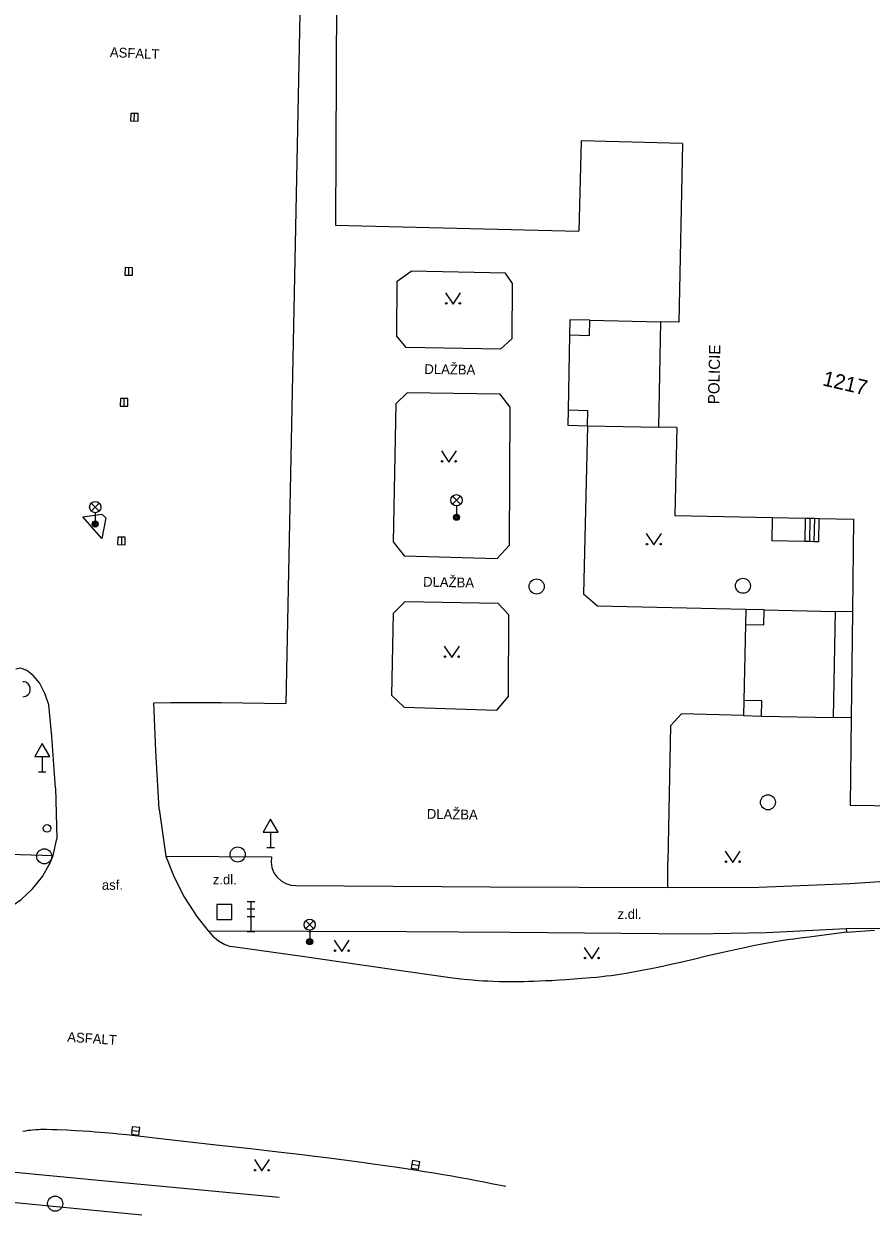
# Model space of a CAD drawing. Extents: x -538441 to -536770, y -1181008 to -1179809.
# Drawn here: x -537395.9 to -537339.6, y -1180903.8 to -1180824.7 of the extents above; entities that cross this region are included whole.
import ezdxf

# ---------------------------------------------------------------- set-up
doc = ezdxf.new("R2010")
doc.units = 0
for name, color, linetype in [('Vrstva 10', 7, 'Continuous'), ('Vrstva 11', 7, 'Continuous'), ('Vrstva 22', 7, 'Continuous'), ('Vrstva 26', 7, 'Continuous'), ('Vrstva 27', 7, 'Continuous'), ('Vrstva 28', 7, 'Continuous'), ('Vrstva 30', 7, 'Continuous'), ('Vrstva 33', 7, 'Continuous'), ('Vrstva 34', 7, 'Continuous'), ('Vrstva 36', 7, 'Continuous'), ('Vrstva 40', 7, 'Continuous'), ('Vrstva 41', 7, 'Continuous'), ('Vrstva 47', 7, 'Continuous'), ('Vrstva 5', 7, 'Continuous')]:
    doc.layers.add(name, color=color, linetype=linetype)

msp = doc.modelspace()

# ---------------------------------------------------------------- linework, layer by layer
at = {"layer": 'Vrstva 10'}
for p, q in [((-537393.79, -1180875.4), (-537393.689, -1180878.783)), ((-537386.911, -1180876.805), (-537386.453, -1180879.925)), ((-537393.943, -1180879.887), (-537393.689, -1180878.783)), ((-537341.271, -1180884.988), (-537339.403, -1180884.851))]:
    msp.add_line(p, q, dxfattribs=at)
for points in [[(-537393.79, -1180875.4), (-537394.04, -1180871.991), (-537394.231, -1180869.894), (-537394.465, -1180869.187), (-537394.848, -1180868.417), (-537395.259, -1180867.947), (-537395.699, -1180867.612), (-537396.093, -1180867.461), (-537396.423, -1180867.524)], [(-537386.911, -1180876.805), (-537387.135, -1180872.945), (-537387.26, -1180869.75)], [(-537396.933, -1180883.407), (-537396.07, -1180882.818), (-537395.306, -1180882.105), (-537394.66, -1180881.283), (-537394.147, -1180880.373), (-537393.943, -1180879.887)], [(-537386.453, -1180879.925), (-537385.911, -1180881.334), (-537385.223, -1180882.678), (-537384.397, -1180883.942), (-537383.644, -1180884.884)], [(-537383.644, -1180884.884), (-537383.333, -1180885.246), (-537382.967, -1180885.552), (-537382.554, -1180885.792), (-537382.173, -1180885.941)], [(-537341.271, -1180884.988), (-537343.735, -1180885.325), (-537344.33, -1180885.39), (-537344.768, -1180885.443), (-537345.191, -1180885.501), (-537345.601, -1180885.562), (-537345.997, -1180885.626), (-537346.381, -1180885.692), (-537346.752, -1180885.759), (-537347.111, -1180885.828), (-537347.459, -1180885.897), (-537348.133, -1180886.036)], [(-537373.444, -1180887.174), (-537377.552, -1180886.587), (-537382.173, -1180885.941)], [(-537348.133, -1180886.036), (-537348.763, -1180886.174), (-537349.354, -1180886.307), (-537350.461, -1180886.564), (-537351.43, -1180886.791), (-537352.278, -1180886.988), (-537353.02, -1180887.156), (-537353.671, -1180887.297), (-537354.24, -1180887.416), (-537354.739, -1180887.515), (-537355.176, -1180887.597), (-537355.558, -1180887.665), (-537355.894, -1180887.722), (-537356.187, -1180887.769), (-537356.444, -1180887.808), (-537356.895, -1180887.871), (-537357.233, -1180887.915), (-537357.487, -1180887.945), (-537357.868, -1180887.985)], [(-537367.59, -1180888.01), (-537369.6, -1180887.723), (-537371.61, -1180887.436), (-537372.527, -1180887.305), (-537373.444, -1180887.174)], [(-537357.868, -1180887.985), (-537358.25, -1180888.02), (-537358.831, -1180888.068), (-537359.377, -1180888.11), (-537359.889, -1180888.146), (-537360.371, -1180888.177), (-537360.823, -1180888.204), (-537361.246, -1180888.225), (-537361.644, -1180888.243), (-537362.017, -1180888.256), (-537362.367, -1180888.267), (-537362.695, -1180888.274), (-537363.002, -1180888.278), (-537363.29, -1180888.28), (-537363.831, -1180888.279), (-537364.303, -1180888.271), (-537364.716, -1180888.258), (-537365.077, -1180888.243), (-537365.392, -1180888.227), (-537365.668, -1180888.209), (-537365.909, -1180888.192), (-537366.331, -1180888.157), (-537366.646, -1180888.126), (-537366.883, -1180888.1), (-537367.237, -1180888.058), (-537367.59, -1180888.01)], [(-537395.953, -1180898.199), (-537395.76, -1180898.166), (-537395.591, -1180898.14), (-537395.443, -1180898.121), (-537395.312, -1180898.107), (-537395.083, -1180898.087), (-537394.911, -1180898.077), (-537394.781, -1180898.071), (-537394.586, -1180898.068), (-537394.39, -1180898.07), (-537394.022, -1180898.08), (-537393.676, -1180898.091), (-537393.027, -1180898.118)], [(-537393.027, -1180898.118), (-537392.459, -1180898.147), (-537391.962, -1180898.177), (-537391.528, -1180898.206), (-537391.147, -1180898.234), (-537390.482, -1180898.288), (-537389.983, -1180898.333), (-537389.609, -1180898.369), (-537389.049, -1180898.427), (-537388.49, -1180898.49), (-537386.609, -1180898.705), (-537383.315, -1180899.073)], [(-537383.315, -1180899.073), (-537380.845, -1180899.351), (-537378.993, -1180899.565), (-537377.604, -1180899.73), (-537376.564, -1180899.857), (-537375.783, -1180899.955), (-537374.613, -1180900.106), (-537373.444, -1180900.262)], [(-537373.444, -1180900.262), (-537372.562, -1180900.384), (-537371.241, -1180900.575), (-537369.92, -1180900.77), (-537369.278, -1180900.868), (-537368.656, -1180900.967), (-537368.055, -1180901.067), (-537367.473, -1180901.167), (-537366.91, -1180901.267), (-537366.365, -1180901.367), (-537365.838, -1180901.467), (-537365.328, -1180901.566), (-537364.834, -1180901.664), (-537363.878, -1180901.859)]]:
    msp.add_lwpolyline(points, dxfattribs=at)
at = {"layer": 'Vrstva 11'}
for p, q in [((-537377.522, -1180822.026), (-537378.49, -1180869.79)), ((-537371.1, -1180841.75), (-537370.16, -1180841.1)), ((-537363.9, -1180841.22), (-537370.16, -1180841.1)), ((-537363.44, -1180841.9), (-537363.9, -1180841.22)), ((-537371.12, -1180845.41), (-537371.1, -1180841.75)), ((-537363.46, -1180845.56), (-537363.44, -1180841.9)), ((-537370.5, -1180846.15), (-537371.12, -1180845.41)), ((-537363.46, -1180845.56), (-537364.24, -1180846.27)), ((-537364.24, -1180846.27), (-537370.5, -1180846.15)), ((-537370.43, -1180849.17), (-537371.19, -1180849.91)), ((-537364.26, -1180849.26), (-537370.43, -1180849.17)), ((-537363.6, -1180850.11), (-537364.26, -1180849.26)), ((-537371.19, -1180849.91), (-537371.37, -1180859.06)), ((-537363.65, -1180859.29), (-537363.6, -1180850.11)), ((-537358.458, -1180851.353), (-537358.73, -1180862.54)), ((-537391.98, -1180857.4), (-537390.7, -1180857.22)), ((-537390.7, -1180857.22), (-537390.44, -1180857.47)), ((-537390.71, -1180858.84), (-537391.98, -1180857.4)), ((-537390.44, -1180857.47), (-537390.71, -1180858.84)), ((-537346.199, -1180857.44), (-537346.23, -1180859)), ((-537343.999, -1180857.485), (-537344.03, -1180859.044)), ((-537343.699, -1180857.491), (-537343.73, -1180859.05)), ((-537343.399, -1180857.497), (-537343.43, -1180859.056)), ((-537343.1, -1180857.503), (-537343.131, -1180859.062)), ((-537371.37, -1180859.06), (-537370.63, -1180859.99)), ((-537364.45, -1180860.16), (-537363.65, -1180859.29)), ((-537370.63, -1180859.99), (-537364.45, -1180860.16)), ((-537357.8, -1180863.33), (-537358.73, -1180862.54)), ((-537370.59, -1180863.04), (-537371.37, -1180863.83)), ((-537364.4, -1180863.16), (-537370.59, -1180863.04)), ((-537363.69, -1180863.9), (-537364.4, -1180863.16)), ((-537347.946, -1180863.55), (-537357.8, -1180863.33)), ((-537371.37, -1180863.83), (-537371.48, -1180869.24)), ((-537363.71, -1180869.34), (-537363.69, -1180863.9)), ((-537371.48, -1180869.24), (-537370.63, -1180870.05)), ((-537364.48, -1180870.23), (-537363.71, -1180869.34)), ((-537370.63, -1180870.05), (-537364.48, -1180870.23)), ((-537352.23, -1180870.49), (-537352.95, -1180871.28)), ((-537348.111, -1180870.602), (-537352.23, -1180870.49)), ((-537352.95, -1180871.28), (-537353.137, -1180880.318)), ((-537401.921, -1180879.666), (-537393.943, -1180879.887)), ((-537386.453, -1180879.925), (-537379.453, -1180879.986)), ((-537353.118, -1180882.017), (-537353.137, -1180880.318)), ((-537341.045, -1180881.75), (-537338.714, -1180881.588)), ((-537377.821, -1180881.878), (-537364.922, -1180881.975)), ((-537364.922, -1180881.975), (-537353.118, -1180882.017)), ((-537353.118, -1180882.017), (-537347.079, -1180882.004)), ((-537347.079, -1180882.004), (-537341.045, -1180881.75)), ((-537383.644, -1180884.884), (-537370.477, -1180884.948)), ((-537346.568, -1180885.001), (-537341.292, -1180884.749)), ((-537341.292, -1180884.749), (-537341.271, -1180884.988)), ((-537370.477, -1180884.948), (-537363.578, -1180884.983)), ((-537363.578, -1180884.983), (-537351.311, -1180885.099)), ((-537351.311, -1180885.099), (-537346.568, -1180885.001)), ((-537401.07, -1180900.47), (-537390, -1180901.53)), ((-537390, -1180901.53), (-537378.93, -1180902.59)), ((-537388.06, -1180903.775), (-537397.13, -1180902.88))]:
    msp.add_line(p, q, dxfattribs=at)
for points in [[(-537343.131, -1180859.062), (-537343.43, -1180859.056), (-537343.73, -1180859.05), (-537344.03, -1180859.044), (-537346.23, -1180859)], [(-537387.26, -1180869.75), (-537386.14, -1180869.737), (-537385.58, -1180869.732), (-537385.02, -1180869.73), (-537384.204, -1180869.732), (-537382.775, -1180869.742), (-537378.49, -1180869.79)], [(-537379.453, -1180879.986), (-537379.475, -1180880.344), (-537379.417, -1180880.699), (-537379.282, -1180881.032), (-537379.091, -1180881.31), (-537378.812, -1180881.569), (-537378.5, -1180881.746), (-537378.157, -1180881.851), (-537377.821, -1180881.878)], [(-537328.346, -1180885.295), (-537328.896, -1180885.216), (-537329.31, -1180885.161), (-537329.621, -1180885.123), (-537330.087, -1180885.071), (-537330.555, -1180885.023), (-537330.979, -1180884.984), (-537331.391, -1180884.949), (-537331.79, -1180884.918), (-537332.177, -1180884.891), (-537332.552, -1180884.868), (-537332.916, -1180884.847), (-537333.269, -1180884.83), (-537333.611, -1180884.815), (-537334.273, -1180884.791), (-537334.895, -1180884.776), (-537335.478, -1180884.768), (-537336.025, -1180884.765), (-537336.538, -1180884.766), (-537337.019, -1180884.771), (-537341.292, -1180884.749)]]:
    msp.add_lwpolyline(points, dxfattribs=at)
at = {"layer": 'Vrstva 22'}
msp.add_arc((-537395.96, -1180868.85), 0.5, 270, 90, dxfattribs=at)
at = {"layer": 'Vrstva 26'}
msp.add_lwpolyline([(-537383.071, -1180884.146), (-537382.071, -1180884.146), (-537382.071, -1180883.146), (-537383.071, -1180883.146)], close=True, dxfattribs=at)
at = {"layer": 'Vrstva 27'}
for p, q in [((-537388.555, -1180831.12), (-537388.545, -1180830.62)), ((-537388.925, -1180841.36), (-537388.915, -1180840.86)), ((-537389.235, -1180850.05), (-537389.225, -1180849.55)), ((-537389.405, -1180858.75), (-537389.415, -1180859.25)), ((-537388.718, -1180898.151), (-537388.222, -1180898.207)), ((-537370.13, -1180900.399), (-537369.636, -1180900.475))]:
    msp.add_line(p, q, dxfattribs=at)
for points in [[(-537388.305, -1180831.125), (-537388.295, -1180830.625), (-537388.795, -1180830.615), (-537388.805, -1180831.115)], [(-537388.675, -1180841.365), (-537388.665, -1180840.865), (-537389.165, -1180840.855), (-537389.175, -1180841.355)], [(-537388.985, -1180850.055), (-537388.975, -1180849.555), (-537389.475, -1180849.545), (-537389.485, -1180850.045)], [(-537389.655, -1180858.745), (-537389.665, -1180859.245), (-537389.165, -1180859.255), (-537389.155, -1180858.755)], [(-537388.746, -1180898.4), (-537388.249, -1180898.455), (-537388.194, -1180897.958), (-537388.691, -1180897.903)], [(-537370.168, -1180900.646), (-537369.674, -1180900.722), (-537369.598, -1180900.228), (-537370.092, -1180900.152)]]:
    msp.add_lwpolyline(points, close=True, dxfattribs=at)
for centre in [(-537361.84, -1180862.03), (-537348.14, -1180861.98), (-537346.48, -1180876.36), (-537381.689, -1180879.824), (-537393.81, -1180903.01)]:
    msp.add_circle(centre, 0.5, dxfattribs=at)
at = {"layer": 'Vrstva 28'}
msp.add_circle((-537394.35, -1180878.09), 0.25, dxfattribs=at)
at = {"layer": 'Vrstva 30'}
msp.add_circle((-537394.533, -1180879.945), 0.5, dxfattribs=at)
at = {"layer": 'Vrstva 33'}
for p, q in [((-537367.425, -1180856.57), (-537366.895, -1180856.04)), ((-537367.425, -1180856.04), (-537366.895, -1180856.57)), ((-537391.415, -1180857.02), (-537390.885, -1180856.49)), ((-537391.415, -1180856.49), (-537390.885, -1180857.02)), ((-537391.15, -1180857.13), (-537391.15, -1180857.88)), ((-537367.16, -1180856.68), (-537367.16, -1180857.43)), ((-537381.05, -1180882.94), (-537380.55, -1180882.94)), ((-537380.8, -1180884.94), (-537380.8, -1180882.94)), ((-537381.05, -1180883.44), (-537380.55, -1180883.44)), ((-537381.05, -1180883.94), (-537380.55, -1180883.94)), ((-537377.175, -1180884.75), (-537376.645, -1180884.22)), ((-537377.175, -1180884.22), (-537376.645, -1180884.75)), ((-537376.91, -1180884.86), (-537376.91, -1180885.61)), ((-537381.05, -1180884.94), (-537380.55, -1180884.94))]:
    msp.add_line(p, q, dxfattribs=at)
for centre, radius in [((-537391.15, -1180856.755), 0.375), ((-537367.16, -1180856.305), 0.375), ((-537391.15, -1180857.88), 0.2), ((-537391.15, -1180857.88), 0.145), ((-537391.15, -1180857.88), 0.0876), ((-537367.16, -1180857.43), 0.2), ((-537367.16, -1180857.43), 0.145), ((-537367.16, -1180857.43), 0.0876), ((-537376.91, -1180884.485), 0.375), ((-537376.91, -1180885.61), 0.2), ((-537376.91, -1180885.61), 0.145), ((-537376.91, -1180885.61), 0.0876)]:
    msp.add_circle(centre, radius, dxfattribs=at)
at = {"layer": 'Vrstva 34'}
for p, q in [((-537394.67, -1180873.314), (-537394.67, -1180874.332)), ((-537394.92, -1180874.332), (-537394.42, -1180874.332)), ((-537379.501, -1180878.335), (-537379.501, -1180879.353)), ((-537379.751, -1180879.353), (-537379.251, -1180879.353))]:
    msp.add_line(p, q, dxfattribs=at)
for points in [[(-537395.17, -1180873.314), (-537394.17, -1180873.314), (-537394.67, -1180872.448)], [(-537380.001, -1180878.335), (-537379.001, -1180878.335), (-537379.501, -1180877.469)]]:
    msp.add_lwpolyline(points, close=True, dxfattribs=at)
at = {"layer": 'Vrstva 36'}
for points in [[(-537367.888, -1180842.529), (-537367.388, -1180843.279), (-537366.888, -1180842.529)], [(-537368.167, -1180853.02), (-537367.667, -1180853.77), (-537367.167, -1180853.02)], [(-537354.559, -1180858.516), (-537354.059, -1180859.266), (-537353.559, -1180858.516)], [(-537367.972, -1180865.989), (-537367.472, -1180866.739), (-537366.972, -1180865.989)], [(-537349.314, -1180879.605), (-537348.814, -1180880.355), (-537348.314, -1180879.605)], [(-537375.277, -1180885.515), (-537374.777, -1180886.265), (-537374.277, -1180885.515)], [(-537358.678, -1180885.999), (-537358.178, -1180886.749), (-537357.678, -1180885.999)], [(-537380.582, -1180900.089), (-537380.082, -1180900.839), (-537379.582, -1180900.089)]]:
    msp.add_lwpolyline(points, dxfattribs=at)
for centre in [(-537367.838, -1180843.229), (-537366.939, -1180843.229), (-537368.117, -1180853.72), (-537367.218, -1180853.72), (-537354.509, -1180859.216), (-537353.61, -1180859.216), (-537367.922, -1180866.689), (-537367.023, -1180866.689), (-537349.264, -1180880.305), (-537348.365, -1180880.305), (-537375.227, -1180886.215), (-537374.328, -1180886.215), (-537358.628, -1180886.699), (-537357.729, -1180886.699), (-537380.532, -1180900.789), (-537379.633, -1180900.789)]:
    msp.add_circle(centre, 0.05, dxfattribs=at)
at = {"layer": 'Vrstva 5'}
for p, q in [((-537375.079, -1180812.769), (-537375.2, -1180838.03)), ((-537358.891, -1180832.438), (-537359.042, -1180838.436)), ((-537352.143, -1180832.608), (-537358.891, -1180832.438)), ((-537352.143, -1180832.608), (-537352.391, -1180844.476)), ((-537375.2, -1180838.03), (-537373.444, -1180838.074)), ((-537373.444, -1180838.074), (-537359.042, -1180838.436)), ((-537359.625, -1180844.327), (-537359.646, -1180845.326)), ((-537358.314, -1180844.354), (-537359.625, -1180844.327)), ((-537358.335, -1180845.353), (-537358.314, -1180844.354)), ((-537358.314, -1180844.354), (-537353.606, -1180844.451)), ((-537353.606, -1180844.451), (-537353.75, -1180851.45)), ((-537352.391, -1180844.476), (-537353.606, -1180844.451)), ((-537359.646, -1180845.326), (-537359.749, -1180850.326)), ((-537359.646, -1180845.326), (-537358.335, -1180845.353)), ((-537359.749, -1180850.326), (-537359.77, -1180851.325)), ((-537358.437, -1180850.354), (-537359.749, -1180850.326)), ((-537358.458, -1180851.353), (-537358.437, -1180850.354)), ((-537359.77, -1180851.325), (-537358.458, -1180851.353)), ((-537358.458, -1180851.353), (-537353.75, -1180851.45)), ((-537352.538, -1180851.475), (-537353.75, -1180851.45)), ((-537352.538, -1180851.475), (-537352.66, -1180857.31)), ((-537347.946, -1180863.55), (-537347.97, -1180864.549)), ((-537346.735, -1180863.579), (-537347.946, -1180863.55)), ((-537346.759, -1180864.578), (-537346.735, -1180863.579)), ((-537346.735, -1180863.579), (-537342.008, -1180863.679)), ((-537342.008, -1180863.679), (-537342.15, -1180870.73)), ((-537340.873, -1180863.702), (-537342.008, -1180863.679)), ((-537347.97, -1180864.549), (-537348.088, -1180869.602)), ((-537347.97, -1180864.549), (-537346.759, -1180864.578)), ((-537348.088, -1180869.602), (-537348.111, -1180870.602)), ((-537346.876, -1180869.63), (-537348.088, -1180869.602)), ((-537346.899, -1180870.63), (-537346.876, -1180869.63)), ((-537348.111, -1180870.602), (-537346.899, -1180870.63)), ((-537346.899, -1180870.63), (-537342.15, -1180870.73)), ((-537340.959, -1180870.754), (-537342.15, -1180870.73)), ((-537341.03, -1180876.56), (-537322.14, -1180876.79))]:
    msp.add_line(p, q, dxfattribs=at)
for points in [[(-537352.66, -1180857.31), (-537346.199, -1180857.44), (-537343.999, -1180857.485), (-537343.699, -1180857.491), (-537343.399, -1180857.497), (-537343.1, -1180857.503), (-537340.798, -1180857.549)], [(-537340.798, -1180857.549), (-537340.873, -1180863.702), (-537340.959, -1180870.754), (-537341.03, -1180876.56)]]:
    msp.add_lwpolyline(points, dxfattribs=at)

# ---------------------------------------------------------------- texts
at = {"layer": 'Vrstva 40'}
for s, rotation, p in [('ASFALT', 357.40574, (-537390.186, -1180826.868)), ('DLAŽBA', 359.1643, (-537369.297, -1180847.913)), ('DLAŽBA', 358.8894, (-537369.382, -1180862.036)), ('DLAŽBA', 358.95588, (-537369.136, -1180877.451)), ('ASFALT', 356.23362, (-537393.021, -1180892.257))]:
    msp.add_text(s, height=0.65, rotation=rotation, dxfattribs=at).set_placement(p)
for s, p in [('asf.', (-537390.709, -1180882.171)), ('z.dl.', (-537383.343, -1180881.81)), ('z.dl.', (-537356.466, -1180884.105))]:
    msp.add_text(s, height=0.65, dxfattribs=at).set_placement(p)
at = {"layer": 'Vrstva 41'}
msp.add_text('POLICIE', height=0.75, rotation=88.82134, dxfattribs=at).set_placement((-537349.718, -1180849.93))
at = {"layer": 'Vrstva 47'}
msp.add_text('1217', height=1, rotation=346.92421, dxfattribs=at).set_placement((-537342.907, -1180848.665))

doc.saveas('drawing.dxf')
